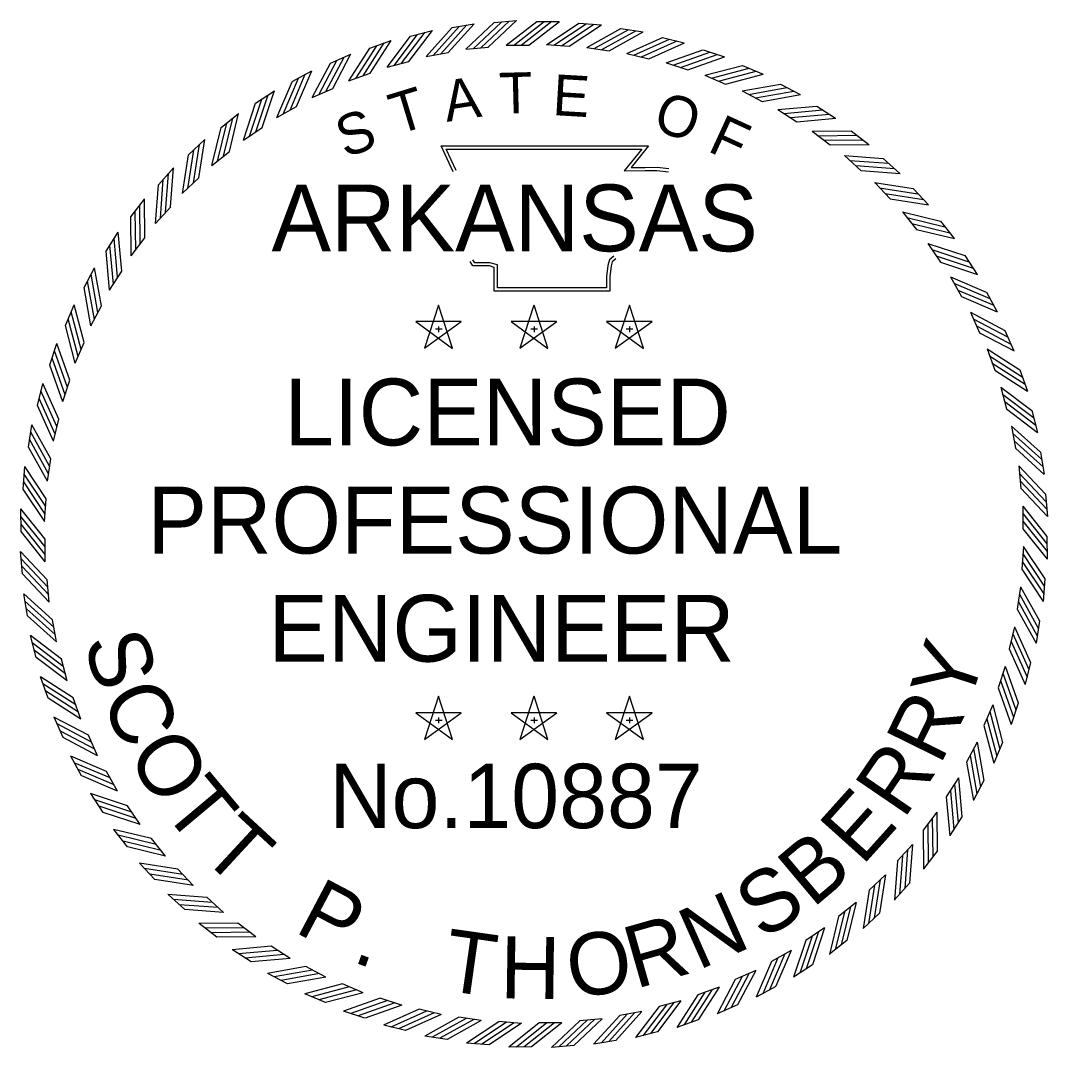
# Model space of a CAD drawing. Extents: x -549 to 3324, y -742 to 2142.
# Drawn here: x 3045 to 3284.3, y 108.2 to 347.4 of the extents above; entities that cross this region are included whole.
import ezdxf

# ---------------------------------------------------------------- set-up
doc = ezdxf.new("R2010")
doc.units = 0
doc.layers.add('STAMP_PP', color=7, linetype='Continuous')

msp = doc.modelspace()

# ---------------------------------------------------------------- linework, layer by layer
at = {"layer": 'STAMP_PP'}
for p, q in [((3155.41, 346.95), (3160.63, 347.44)), ((3165.33, 347.25), (3170.57, 347.25)), ((3135.92, 343.8), (3140.99, 345.14)), ((3145.6, 345.78), (3150.76, 346.69)), ((3175.15, 346.85), (3180.37, 346.47)), ((3184.94, 345.58), (3190.12, 344.77)), ((3126.44, 341.03), (3131.38, 342.78)), ((3194.6, 343.51), (3199.69, 342.27)), ((3139.53, 339.05), (3144.7, 339.96)), ((3148.8, 340.75), (3154.03, 341.23)), ((3158.18, 341.67), (3163.43, 341.67)), ((3167.61, 341.82), (3172.84, 341.43)), ((3177.01, 341.19), (3182.2, 340.37)), ((3186.33, 339.78), (3191.44, 338.54)), ((3204.05, 340.64), (3209.02, 338.98)), ((3117.22, 337.49), (3122, 339.64)), ((3130.43, 336.59), (3135.5, 337.93)), ((3195.51, 337.61), (3200.49, 335.95)), ((3108.32, 333.2), (3112.91, 335.73)), ((3121.56, 333.39), (3126.51, 335.14)), ((3213.24, 337), (3218.05, 334.94)), ((3204.47, 334.69), (3209.3, 332.62)), ((3222.09, 332.62), (3226.72, 330.17)), ((3099.81, 328.19), (3104.17, 331.09)), ((3112.99, 329.47), (3117.78, 331.63)), ((3213.16, 331.03), (3217.8, 328.58)), ((3091.74, 322.49), (3095.85, 325.74)), ((3104.77, 324.86), (3109.36, 327.4)), ((3221.52, 326.68), (3225.94, 323.85)), ((3230.55, 327.52), (3234.96, 324.69)), ((3096.96, 319.58), (3101.33, 322.49)), ((3229.49, 321.65), (3233.66, 318.46)), ((3238.56, 321.74), (3242.72, 318.56)), ((3084.17, 316.14), (3088, 319.73)), ((3089.61, 313.67), (3093.72, 316.94)), ((3237.02, 315.97), (3240.92, 312.45)), ((3246.06, 315.31), (3249.95, 311.8)), ((3077.15, 309.19), (3080.67, 313.08)), ((3082.77, 307.18), (3086.6, 310.77)), ((3244.05, 309.7), (3247.65, 305.87)), ((3253.01, 308.29), (3256.6, 304.47)), ((3070.73, 301.69), (3073.91, 305.85)), ((3076.5, 300.15), (3080.02, 304.04)), ((3250.54, 302.86), (3253.81, 298.75)), ((3259.36, 300.72), (3262.61, 296.62)), ((3064.95, 293.68), (3067.78, 298.09)), ((3070.82, 292.62), (3074.01, 296.79)), ((3256.45, 295.51), (3259.36, 291.14)), ((3265.06, 292.66), (3267.96, 288.3)), ((3059.85, 285.22), (3062.3, 289.85)), ((3065.79, 284.65), (3068.62, 289.07)), ((3261.73, 287.7), (3264.27, 283.11)), ((3270.07, 284.14), (3272.6, 279.56)), ((3055.47, 276.37), (3057.53, 281.18)), ((3061.43, 276.29), (3063.89, 280.93)), ((3142.43, 281.13), (3139.15, 271.07)), ((3145.7, 271.08), (3142.44, 281.14)), ((3164.66, 281.13), (3161.38, 271.07)), ((3167.93, 271.08), (3164.67, 281.14)), ((3186.89, 281.13), (3183.61, 271.07)), ((3190.15, 271.08), (3186.89, 281.14)), ((3266.34, 279.48), (3268.5, 274.69)), ((3147.72, 277.29), (3137.14, 277.3)), ((3137.15, 277.29), (3145.7, 271.06)), ((3139.17, 271.08), (3147.73, 277.29)), ((3141.68, 275.6), (3143.25, 275.6)), ((3142.44, 276.17), (3142.44, 274.84)), ((3169.94, 277.29), (3159.37, 277.3)), ((3159.38, 277.29), (3167.93, 271.06)), ((3161.39, 271.08), (3169.96, 277.29)), ((3163.91, 275.6), (3165.48, 275.6)), ((3164.67, 276.17), (3164.67, 274.84)), ((3192.17, 277.29), (3181.59, 277.3)), ((3181.6, 277.29), (3190.15, 271.06)), ((3183.62, 271.08), (3192.19, 277.29)), ((3186.13, 275.6), (3187.71, 275.6)), ((3186.9, 276.17), (3186.9, 274.84)), ((3274.36, 275.25), (3276.51, 270.47)), ((3051.83, 267.18), (3053.49, 272.15)), ((3057.78, 267.6), (3059.85, 272.43)), ((3270.26, 270.91), (3272.02, 265.96)), ((3277.91, 266.03), (3279.65, 261.09)), ((3054.86, 258.64), (3056.52, 263.62)), ((3048.96, 257.73), (3050.2, 262.82)), ((3273.46, 262.04), (3274.8, 256.96)), ((3280.68, 256.55), (3282.01, 251.48)), ((3052.69, 249.46), (3053.93, 254.57)), ((3046.89, 248.07), (3047.7, 253.25)), ((3275.92, 252.94), (3276.83, 247.77)), ((3282.65, 246.87), (3283.56, 241.71)), ((3051.28, 240.14), (3052.1, 245.33)), ((3045.62, 238.28), (3046, 243.5)), ((3277.62, 243.67), (3278.1, 238.44)), ((3283.82, 237.06), (3284.31, 231.84)), ((3050.65, 230.74), (3051.04, 235.97)), ((3045.16, 228.41), (3045.11, 233.65)), ((3278.54, 234.29), (3278.59, 229.04)), ((3050.8, 221.31), (3050.75, 226.56)), ((3284.18, 227.19), (3284.23, 221.95)), ((3045.51, 218.54), (3045.03, 223.76)), ((3278.69, 224.86), (3278.3, 219.63)), ((3051.72, 211.93), (3051.24, 217.16)), ((3278.06, 215.46), (3277.24, 210.27)), ((3283.72, 217.32), (3283.34, 212.1)), ((3046.69, 208.73), (3045.78, 213.89)), ((3053.42, 202.66), (3052.51, 207.83)), ((3276.65, 206.14), (3275.41, 201.03)), ((3282.45, 207.53), (3281.64, 202.35)), ((3048.66, 199.05), (3047.33, 204.12)), ((3055.88, 193.55), (3054.54, 198.63)), ((3274.48, 196.96), (3272.82, 191.98)), ((3280.38, 197.87), (3279.14, 192.78)), ((3051.43, 189.57), (3049.69, 194.51)), ((3059.08, 184.69), (3057.32, 189.64)), ((3142.43, 189.99), (3139.15, 179.94)), ((3145.7, 179.94), (3142.44, 190.01)), ((3164.66, 189.99), (3161.38, 179.94)), ((3167.93, 179.94), (3164.67, 190.01)), ((3186.89, 189.99), (3183.61, 179.94)), ((3190.15, 179.94), (3186.89, 190.01)), ((3271.56, 188), (3269.49, 183.17)), ((3277.51, 188.42), (3275.85, 183.45)), ((3054.98, 180.35), (3052.83, 185.13)), ((3147.72, 186.15), (3137.14, 186.16)), ((3137.15, 186.15), (3145.7, 179.93)), ((3139.17, 179.94), (3147.73, 186.15)), ((3141.68, 184.46), (3143.25, 184.46)), ((3142.44, 185.03), (3142.44, 183.7)), ((3169.94, 186.15), (3159.37, 186.16)), ((3159.38, 186.15), (3167.93, 179.93)), ((3161.39, 179.94), (3169.96, 186.15)), ((3163.91, 184.46), (3165.48, 184.46)), ((3164.67, 185.03), (3164.67, 183.7)), ((3192.17, 186.15), (3181.59, 186.16)), ((3181.6, 186.15), (3190.15, 179.93)), ((3183.62, 179.94), (3192.19, 186.15)), ((3186.13, 184.46), (3187.71, 184.46)), ((3186.9, 185.03), (3186.9, 183.7)), ((3063, 176.12), (3060.84, 180.91)), ((3267.91, 179.31), (3265.45, 174.67)), ((3273.87, 179.23), (3271.81, 174.42)), ((3059.27, 171.45), (3056.73, 176.04)), ((3067.61, 167.9), (3065.07, 172.49)), ((3263.55, 170.95), (3260.72, 166.53)), ((3269.49, 170.38), (3267.04, 165.75)), ((3064.28, 162.94), (3061.38, 167.3)), ((3072.89, 160.09), (3069.98, 164.46)), ((3258.52, 162.98), (3255.33, 158.81)), ((3264.39, 161.92), (3261.56, 157.51)), ((3069.98, 154.87), (3066.73, 158.98)), ((3078.8, 152.74), (3075.53, 156.85)), ((3252.84, 155.45), (3249.32, 151.55)), ((3258.61, 153.91), (3255.43, 149.75)), ((3076.33, 147.3), (3072.74, 151.13)), ((3085.29, 145.9), (3081.69, 149.73)), ((3246.57, 148.42), (3242.74, 144.82)), ((3252.19, 146.41), (3248.67, 142.52)), ((3083.28, 140.28), (3079.39, 143.8)), ((3092.32, 139.63), (3088.42, 143.15)), ((3239.73, 141.93), (3235.62, 138.66)), ((3245.17, 139.46), (3241.34, 135.87)), ((3090.78, 133.86), (3086.62, 137.04)), ((3099.85, 133.95), (3095.68, 137.14)), ((3232.38, 136.02), (3228.01, 133.11)), ((3107.82, 128.92), (3103.4, 131.75)), ((3237.59, 133.11), (3233.49, 129.86)), ((3098.79, 128.08), (3094.38, 130.91)), ((3224.57, 130.74), (3219.98, 128.2)), ((3116.18, 124.56), (3111.54, 127.02)), ((3229.53, 127.41), (3225.17, 124.51)), ((3107.25, 122.98), (3102.62, 125.43)), ((3216.35, 126.13), (3211.56, 123.97)), ((3124.87, 120.91), (3120.04, 122.98)), ((3207.78, 122.21), (3202.83, 120.45)), ((3221.02, 122.4), (3216.43, 119.86)), ((3116.1, 118.6), (3111.29, 120.66)), ((3133.83, 117.99), (3128.85, 119.65)), ((3198.91, 119.01), (3193.83, 117.67)), ((3212.12, 118.11), (3207.34, 115.96)), ((3125.29, 114.96), (3120.32, 116.62)), ((3143.01, 115.82), (3137.9, 117.06)), ((3152.33, 114.41), (3147.14, 115.23)), ((3189.81, 116.55), (3184.64, 115.64)), ((3134.74, 112.09), (3129.65, 113.33)), ((3161.73, 113.78), (3156.5, 114.17)), ((3171.16, 113.93), (3165.91, 113.88)), ((3180.54, 114.85), (3175.31, 114.37)), ((3202.9, 114.56), (3197.96, 112.82)), ((3144.4, 110.02), (3139.22, 110.83)), ((3193.42, 111.79), (3188.35, 110.46)), ((3154.19, 108.75), (3148.97, 109.13)), ((3164.06, 108.29), (3158.82, 108.24)), ((3173.93, 108.64), (3168.71, 108.16)), ((3183.74, 109.82), (3178.58, 108.91))]:
    msp.add_line(p, q, dxfattribs=at)
for points in [[(3150.47, 340.88), (3157.08, 347.09)], [(3152.28, 341.09), (3158.89, 347.3)], [(3154.02, 341.23), (3160.63, 347.44)], [(3158.17, 341.67), (3165.32, 347.24)], [(3159.86, 341.65), (3167.01, 347.23)], [(3161.68, 341.69), (3168.83, 347.27)], [(3163.43, 341.67), (3170.58, 347.25)], [(3133.81, 337.5), (3139.3, 344.71)], [(3135.5, 337.93), (3140.99, 345.14)], [(3139.52, 339.04), (3145.59, 345.78)], [(3141.18, 339.32), (3147.26, 346.05)], [(3142.97, 339.68), (3149.04, 346.41)], [(3144.69, 339.96), (3150.76, 346.7)], [(3148.79, 340.74), (3155.4, 346.95)], [(3167.6, 341.81), (3175.14, 346.85)], [(3169.28, 341.67), (3176.82, 346.71)], [(3171.1, 341.58), (3178.64, 346.62)], [(3172.84, 341.44), (3180.38, 346.47)], [(3177, 341.18), (3184.93, 345.58)], [(3178.67, 340.9), (3186.6, 345.3)], [(3180.47, 340.66), (3188.4, 345.06)], [(3182.19, 340.37), (3190.12, 344.77)], [(3124.85, 334.58), (3129.73, 342.22)], [(3126.5, 335.15), (3131.38, 342.79)], [(3130.42, 336.59), (3135.92, 343.8)], [(3132.06, 337), (3137.55, 344.21)], [(3186.33, 339.78), (3194.59, 343.5)], [(3187.96, 339.36), (3196.23, 343.09)], [(3189.74, 338.97), (3198, 342.7)], [(3191.43, 338.54), (3199.7, 342.27)], [(3121.55, 333.39), (3126.44, 341.03)], [(3123.15, 333.93), (3128.03, 341.58)], [(3195.5, 337.61), (3204.04, 340.64)], [(3197.09, 337.06), (3205.64, 340.09)], [(3112.98, 329.47), (3117.22, 337.48)], [(3114.53, 330.14), (3118.76, 338.16)], [(3116.17, 330.93), (3120.4, 338.94)], [(3117.77, 331.63), (3122, 339.65)], [(3198.83, 336.52), (3207.38, 339.55)], [(3200.48, 335.95), (3209.03, 338.98)], [(3109.35, 327.4), (3112.91, 335.74)], [(3204.46, 334.68), (3213.23, 337)], [(3206.01, 334.01), (3214.77, 336.32)], [(3207.69, 333.33), (3216.46, 335.64)], [(3104.76, 324.85), (3108.32, 333.19)], [(3106.25, 325.65), (3109.8, 333.99)], [(3107.82, 326.57), (3111.38, 334.91)], [(3209.29, 332.63), (3218.06, 334.94)], [(3213.15, 331.03), (3222.08, 332.62)], [(3101.32, 322.49), (3104.18, 331.1)], [(3214.63, 330.23), (3223.56, 331.81)], [(3216.26, 329.41), (3225.19, 331)], [(3096.95, 319.57), (3099.81, 328.18)], [(3098.37, 320.49), (3101.22, 329.1)], [(3099.86, 321.54), (3102.71, 330.14)], [(3217.8, 328.58), (3226.73, 330.17)], [(3093.72, 316.94), (3095.85, 325.75)], [(3221.51, 326.68), (3230.54, 327.52)], [(3222.92, 325.75), (3231.95, 326.6)], [(3224.48, 324.81), (3233.51, 325.65)], [(3090.94, 314.7), (3093.07, 323.51)], [(3092.34, 315.86), (3094.47, 324.68)], [(3225.94, 323.85), (3234.97, 324.69)], [(3089.61, 313.67), (3091.74, 322.48)], [(3229.48, 321.65), (3238.55, 321.74)], [(3230.81, 320.61), (3239.88, 320.7)], [(3085.31, 309.59), (3086.71, 318.55)], [(3086.6, 310.77), (3088, 319.73)], [(3145.81, 312.17), (3143.01, 318.22), (3191.34, 318.25), (3187.31, 313.18), (3190.59, 313.22), (3193.33, 313.26), (3196.07, 312.96)], [(3232.28, 319.54), (3241.35, 319.63)], [(3233.66, 318.46), (3242.73, 318.56)], [(3082.77, 307.17), (3084.17, 316.13)], [(3084.01, 308.32), (3085.41, 317.27)], [(3146.5, 312.5), (3144.21, 317.46), (3189.76, 317.49), (3185.7, 312.39), (3190.6, 312.46), (3193.3, 312.49), (3195.99, 312.2)], [(3237.01, 315.97), (3246.05, 315.32)], [(3238.25, 314.83), (3247.29, 314.17)], [(3239.63, 313.64), (3248.67, 312.98)], [(3078.83, 302.76), (3079.49, 311.8)], [(3080.01, 304.04), (3080.67, 313.09)], [(3240.91, 312.46), (3249.96, 311.8)], [(3076.5, 300.14), (3077.15, 309.18)], [(3077.64, 301.38), (3078.3, 310.42)], [(3244.04, 309.7), (3253, 308.3)], [(3245.19, 308.46), (3254.14, 307.06)], [(3246.46, 307.16), (3255.42, 305.76)], [(3072.93, 295.41), (3072.84, 304.48)], [(3074, 296.79), (3073.91, 305.86)], [(3247.64, 305.87), (3256.6, 304.47)], [(3070.82, 292.61), (3070.73, 301.68)], [(3071.86, 293.94), (3071.77, 303.01)], [(3250.54, 302.86), (3259.35, 300.73)], [(3251.57, 301.53), (3260.38, 299.4)], [(3252.74, 300.13), (3261.55, 298)], [(3068.62, 289.07), (3067.78, 298.1)], [(3253.81, 298.75), (3262.62, 296.62)], [(3066.71, 286.05), (3065.87, 295.08)], [(3067.66, 287.61), (3066.82, 296.64)], [(3256.44, 295.52), (3265.05, 292.66)], [(3065.79, 284.64), (3064.95, 293.67)], [(3183.73, 291.92), (3182.9, 291.25), (3182.63, 290.25), (3182.36, 287.74), (3182.36, 284.4), (3155.38, 284.4), (3155.38, 288.91), (3155.38, 289.91), (3154.28, 290.25), (3150.45, 290.25), (3149.76, 291.29)], [(3183.24, 292.52), (3182.23, 291.69), (3181.88, 290.39), (3181.59, 287.79), (3181.59, 285.17), (3156.14, 285.17), (3156.14, 288.91), (3156.14, 290.48), (3154.4, 291.01), (3150.86, 291.01), (3150.4, 291.71)], [(3257.36, 294.1), (3265.97, 291.25)], [(3258.41, 292.61), (3267.01, 289.76)], [(3063.89, 280.93), (3062.3, 289.85)], [(3259.36, 291.15), (3267.97, 288.29)], [(3063.05, 279.39), (3061.47, 288.32)], [(3261.72, 287.71), (3270.06, 284.15)], [(3061.44, 276.28), (3059.85, 285.21)], [(3062.24, 277.76), (3060.66, 286.69)], [(3262.52, 286.22), (3270.86, 282.67)], [(3263.44, 284.65), (3271.78, 281.09)], [(3264.27, 283.11), (3272.61, 279.56)], [(3059.84, 272.42), (3057.53, 281.19)], [(3058.46, 269.13), (3056.15, 277.9)], [(3059.14, 270.82), (3056.83, 279.59)], [(3266.34, 279.49), (3274.35, 275.25)], [(3267.01, 277.94), (3275.03, 273.71)], [(3057.79, 267.59), (3055.47, 276.36)], [(3267.8, 276.3), (3275.81, 272.07)], [(3268.5, 274.7), (3276.52, 270.47)], [(3055.95, 261.96), (3052.92, 270.51)], [(3056.52, 263.61), (3053.48, 272.16)], [(3270.26, 270.92), (3277.9, 266.03)], [(3055.41, 260.22), (3052.38, 268.77)], [(3270.8, 269.32), (3278.45, 264.44)], [(3054.86, 258.63), (3051.83, 267.17)], [(3271.45, 267.62), (3279.09, 262.74)], [(3272.02, 265.97), (3279.66, 261.08)], [(3053.5, 252.87), (3049.77, 261.13)], [(3053.93, 254.56), (3050.2, 262.83)], [(3273.46, 262.05), (3280.67, 256.55)], [(3053.11, 251.09), (3049.38, 259.36)], [(3273.87, 260.41), (3281.08, 254.92)], [(3274.37, 258.66), (3281.58, 253.17)], [(3052.69, 249.46), (3048.97, 257.72)], [(3274.8, 256.97), (3282.01, 251.48)], [(3051.81, 243.6), (3047.41, 251.53)], [(3052.1, 245.32), (3047.7, 253.25)], [(3275.91, 252.95), (3282.65, 246.88)], [(3276.19, 251.28), (3282.92, 245.21)], [(3051.57, 241.8), (3047.17, 249.73)], [(3276.55, 249.5), (3283.28, 243.43)], [(3051.29, 240.13), (3046.89, 248.06)], [(3276.83, 247.78), (3283.57, 241.7)], [(3050.89, 234.23), (3045.85, 241.77)], [(3051.03, 235.97), (3046, 243.51)], [(3277.61, 243.68), (3283.82, 237.07)], [(3277.75, 242), (3283.96, 235.39)], [(3050.8, 232.41), (3045.76, 239.95)], [(3277.96, 240.19), (3284.17, 233.58)], [(3050.66, 230.73), (3045.62, 238.27)], [(3278.1, 238.45), (3284.31, 231.84)], [(3050.75, 226.56), (3045.11, 233.65)], [(3278.54, 234.3), (3284.18, 227.2)], [(3278.54, 232.61), (3284.18, 225.51)], [(3050.75, 224.81), (3045.11, 231.91)], [(3050.8, 222.99), (3045.16, 230.09)], [(3278.59, 230.79), (3284.23, 223.69)], [(3050.8, 221.3), (3045.16, 228.4)], [(3278.59, 229.04), (3284.23, 221.94)], [(3051.24, 217.15), (3045.03, 223.76)], [(3278.54, 223.19), (3283.58, 215.65)], [(3278.68, 224.87), (3283.72, 217.33)], [(3051.38, 215.41), (3045.17, 222.02)], [(3051.59, 213.6), (3045.38, 220.21)], [(3278.45, 221.37), (3283.49, 213.83)], [(3051.73, 211.92), (3045.52, 218.53)], [(3278.31, 219.63), (3283.34, 212.09)], [(3278.05, 215.46), (3282.45, 207.53)], [(3052.51, 207.82), (3045.77, 213.89)], [(3277.77, 213.8), (3282.17, 205.87)], [(3052.79, 206.1), (3046.06, 212.17)], [(3277.53, 212), (3281.93, 204.07)], [(3053.15, 204.31), (3046.42, 210.39)], [(3053.43, 202.65), (3046.69, 208.72)], [(3277.24, 210.27), (3281.64, 202.35)], [(3276.65, 206.14), (3280.37, 197.88)], [(3054.54, 198.63), (3047.33, 204.12)], [(3276.23, 204.51), (3279.96, 196.24)], [(3054.97, 196.94), (3047.76, 202.43)], [(3275.41, 201.04), (3279.14, 192.77)], [(3275.84, 202.73), (3279.57, 194.46)], [(3055.47, 195.19), (3048.26, 200.68)], [(3055.88, 193.55), (3048.67, 199.05)], [(3274.48, 196.97), (3277.51, 188.43)], [(3057.32, 189.63), (3049.68, 194.51)], [(3273.93, 195.38), (3276.96, 186.83)], [(3057.89, 187.98), (3050.25, 192.86)], [(3272.82, 191.98), (3275.86, 183.44)], [(3273.39, 193.64), (3276.42, 185.09)], [(3058.53, 186.28), (3050.89, 191.16)], [(3059.08, 184.68), (3051.44, 189.57)], [(3271.55, 188.01), (3273.87, 179.24)], [(3060.84, 180.9), (3052.82, 185.13)], [(3270.2, 184.77), (3272.51, 176.01)], [(3270.88, 186.46), (3273.19, 177.7)], [(3061.54, 179.3), (3053.53, 183.53)], [(3062.33, 177.66), (3054.31, 181.89)], [(3269.5, 183.18), (3271.81, 174.41)], [(3063, 176.11), (3054.99, 180.35)], [(3267.1, 177.83), (3268.68, 168.91)], [(3267.9, 179.32), (3269.49, 170.39)], [(3065.07, 172.48), (3056.73, 176.04)], [(3266.28, 176.21), (3267.87, 167.28)], [(3065.9, 170.95), (3057.56, 174.51)], [(3066.82, 169.38), (3058.48, 172.93)], [(3265.45, 174.67), (3267.04, 165.74)], [(3067.62, 167.89), (3059.28, 171.45)], [(3263.55, 170.96), (3264.39, 161.93)], [(3261.68, 167.99), (3262.52, 158.96)], [(3262.63, 169.55), (3263.47, 160.52)], [(3069.98, 164.45), (3061.37, 167.3)], [(3070.93, 162.99), (3062.33, 165.84)], [(3260.72, 166.53), (3261.56, 157.5)], [(3071.98, 161.49), (3063.37, 164.35)], [(3072.9, 160.08), (3064.29, 162.94)], [(3258.52, 162.99), (3258.61, 153.92)], [(3257.48, 161.66), (3257.57, 152.59)], [(3075.53, 156.85), (3066.72, 158.98)], [(3255.34, 158.81), (3255.43, 149.74)], [(3256.41, 160.19), (3256.5, 151.12)], [(3076.6, 155.47), (3067.79, 157.6)], [(3077.77, 154.07), (3068.96, 156.2)], [(3078.8, 152.74), (3069.99, 154.87)], [(3251.7, 154.22), (3251.04, 145.17)], [(3252.84, 155.46), (3252.19, 146.42)], [(3081.7, 149.73), (3072.74, 151.13)], [(3249.33, 151.56), (3248.67, 142.51)], [(3250.51, 152.84), (3249.85, 143.8)], [(3082.88, 148.44), (3073.92, 149.84)], [(3084.15, 147.14), (3075.19, 148.54)], [(3246.57, 148.42), (3245.17, 139.47)], [(3085.3, 145.9), (3076.34, 147.3)], [(3244.03, 146.01), (3242.63, 137.05)], [(3245.33, 147.28), (3243.93, 138.32)], [(3088.43, 143.14), (3079.38, 143.8)], [(3242.74, 144.83), (3241.34, 135.87)], [(3089.71, 141.96), (3080.67, 142.62)], [(3091.09, 140.77), (3082.05, 141.43)], [(3239.73, 141.93), (3237.6, 133.12)], [(3092.33, 139.63), (3083.29, 140.28)], [(3237, 139.73), (3234.87, 130.92)], [(3238.4, 140.9), (3236.27, 132.09)], [(3095.68, 137.13), (3086.61, 137.04)], [(3235.62, 138.66), (3233.49, 129.85)], [(3097.06, 136.06), (3087.99, 135.97)], [(3098.53, 134.99), (3089.46, 134.9)], [(3229.48, 134.06), (3226.63, 125.46)], [(3230.97, 135.1), (3228.12, 126.5)], [(3232.39, 136.03), (3229.53, 127.42)], [(3099.86, 133.95), (3090.79, 133.86)], [(3103.4, 131.75), (3094.37, 130.91)], [(3228.02, 133.11), (3225.16, 124.5)], [(3104.86, 130.79), (3095.83, 129.95)], [(3106.42, 129.84), (3097.39, 129)], [(3223.09, 129.95), (3219.54, 121.61)], [(3224.58, 130.75), (3221.02, 122.41)], [(3107.83, 128.92), (3098.8, 128.08)], [(3111.54, 127.02), (3102.61, 125.43)], [(3219.98, 128.2), (3216.43, 119.86)], [(3221.52, 129.03), (3217.96, 120.69)], [(3113.08, 126.18), (3104.15, 124.6)], [(3114.71, 125.37), (3105.78, 123.78)], [(3116.19, 124.57), (3107.26, 122.98)], [(3213.17, 124.67), (3208.94, 116.65)], [(3214.81, 125.46), (3210.58, 117.44)], [(3216.36, 126.13), (3212.12, 118.12)], [(3120.05, 122.97), (3111.28, 120.66)], [(3121.64, 122.27), (3112.88, 119.96)], [(3207.79, 122.21), (3202.9, 114.57)], [(3211.57, 123.97), (3207.34, 115.95)], [(3123.33, 121.59), (3114.57, 119.28)], [(3124.88, 120.91), (3116.11, 118.6)], [(3128.86, 119.65), (3120.31, 116.61)], [(3202.84, 120.45), (3197.96, 112.81)], [(3204.49, 121.02), (3199.61, 113.38)], [(3206.19, 121.66), (3201.31, 114.02)], [(3130.51, 119.08), (3121.96, 116.05)], [(3132.25, 118.54), (3123.7, 115.51)], [(3133.84, 117.99), (3125.3, 114.96)], [(3193.84, 117.67), (3188.35, 110.46)], [(3195.53, 118.1), (3190.04, 110.88)], [(3197.28, 118.6), (3191.79, 111.39)], [(3198.92, 119.01), (3193.42, 111.8)], [(3137.91, 117.06), (3129.64, 113.33)], [(3139.6, 116.63), (3131.34, 112.9)], [(3141.38, 116.24), (3133.11, 112.51)], [(3143.01, 115.82), (3134.75, 112.1)], [(3147.15, 115.23), (3139.22, 110.83)], [(3148.87, 114.94), (3140.94, 110.54)], [(3180.55, 114.86), (3173.94, 108.65)], [(3184.65, 115.63), (3178.57, 108.9)], [(3186.37, 115.92), (3180.3, 109.19)], [(3188.16, 116.28), (3182.08, 109.54)], [(3189.82, 116.56), (3183.75, 109.82)], [(3150.67, 114.69), (3142.74, 110.3)], [(3152.34, 114.42), (3144.41, 110.02)], [(3156.5, 114.16), (3148.96, 109.13)], [(3158.24, 114.02), (3150.7, 108.98)], [(3160.06, 113.93), (3152.52, 108.89)], [(3161.74, 113.79), (3154.2, 108.75)], [(3165.91, 113.88), (3158.82, 108.23)], [(3167.66, 113.88), (3160.56, 108.23)], [(3169.48, 113.93), (3162.38, 108.29)], [(3171.17, 113.93), (3164.07, 108.29)], [(3175.32, 114.37), (3168.71, 108.16)], [(3177.06, 114.51), (3170.45, 108.3)], [(3178.87, 114.72), (3172.26, 108.51)]]:
    msp.add_lwpolyline(points, dxfattribs=at)

# ---------------------------------------------------------------- texts
for s, height, rotation, p in [('T', 9.53, 1.4789, (3156.65, 325.71)), ('A', 9.53, 8.6788, (3144.33, 323.81)), ('E', 9.53, 356.672, (3168.85, 325.42)), ('T', 9.53, 16.9015, (3132.76, 320.79)), ('O', 9.53, 341.2218, (3191.99, 322.15)), ('S', 9.53, 19.7726, (3120.64, 315.35)), ('F', 9.53, 335.3628, (3204.84, 317.12)), ('S', 14.48, 286.9475, (3059.58, 202.81)), ('Y', 14.48, 71.7733, (3265.88, 187.37)), ('C', 14.48, 294.2435, (3063.61, 189.61)), ('R', 14.48, 63.7477, (3259.25, 173.7)), ('O', 14.48, 301.9044, (3069.61, 176.41)), ('R', 14.48, 55.7221, (3250.78, 161.1)), ('T', 14.48, 309.93, (3077.71, 163.57)), ('E', 14.48, 48.0613, (3241.12, 150.28)), ('T', 14.48, 317.226, (3086.58, 152.98)), ('B', 14.48, 40.0357, (3229.56, 140.44)), ('S', 14.48, 32.7397, (3217.94, 132.97)), ('P', 14.48, 332.1828, (3108.55, 135.23)), ('N', 14.48, 23.9845, (3202.9, 126.04)), ('R', 14.48, 15.9589, (3188.32, 121.77)), ('T', 14.48, 351.882, (3143.06, 121.55)), ('H', 14.48, 359.178, (3156.73, 119.61)), ('O', 14.48, 7.9332, (3173.3, 119.58)), ('.', 14.48, 340.2084, (3122.02, 128.23))]:
    msp.add_text(s, height=height, rotation=rotation, dxfattribs=at).set_placement(p)
for s, height, p in [('ARKANSAS', 15.559, (3103.51, 293.66)), ('LICENSED', 15.559, (3106.47, 248.44)), ('PROFESSIONAL', 15.5591, (3074.61, 223.25)), ('ENGINEER', 15.559, (3102.77, 198.06)), ('No.10887', 15.003, (3116.99, 159.26))]:
    msp.add_text(s, height=height, dxfattribs=at).set_placement(p)

doc.saveas('drawing.dxf')
